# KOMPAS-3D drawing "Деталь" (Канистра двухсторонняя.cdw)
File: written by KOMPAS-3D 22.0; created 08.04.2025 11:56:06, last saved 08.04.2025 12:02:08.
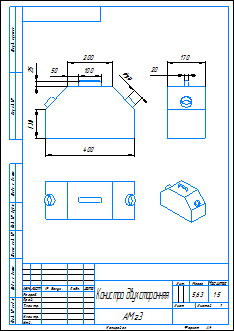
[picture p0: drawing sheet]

Sheet 1: A4, portrait

Document properties: Автор: Admin; Масса: 5.629388; Полное имя файла: Канистра двухсторонняя.m3d

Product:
- Part/product: Деталь
    Масса: 5.629388

Title block, sheet 1: Наименование: Канистра двухсторонняя; Материал: АМг3; Масса: 5,63; Количество листов документа: 1; Форматы листов документа: A4; stored path: D:\28.11.2016\Абилимпикс\2025\Канистра двухсторонняя.cdw

Views: Вид 1, Спереди, Проекционный вид 2, Проекционный вид 3, Проекционный вид 4
Referenced files in D:\28.11.2016\Абилимпикс\2025\: Канистра двухсторонняя.m3d
Dimensions and other numbers on the sheet: 100; 25; 200; 400; 130; 50; 170; 20; 2; 1:5; 1; 5,63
